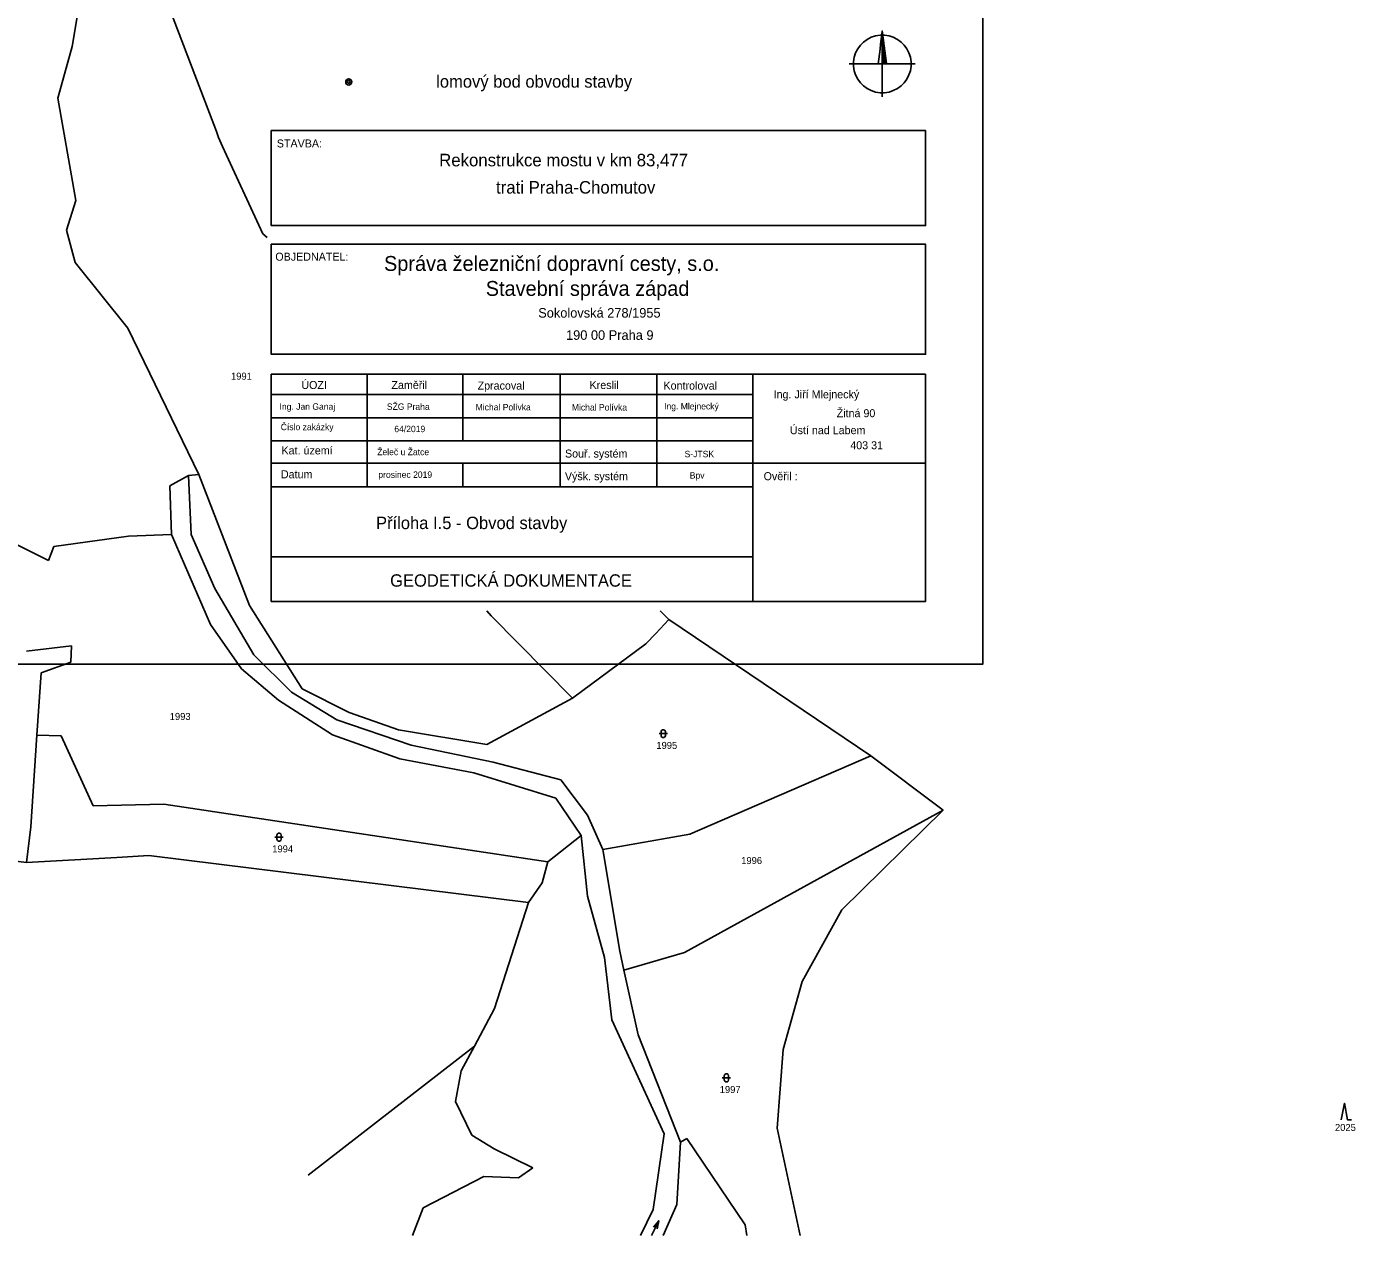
# Model space of a CAD drawing. Extents: x -801853 to -800578, y -1017479 to -1016338.
# Drawn here: x -800950 to -800627.9, y -1017477.7 to -1017184.4 of the extents above; entities that cross this region are included whole.
import ezdxf

# ---------------------------------------------------------------- set-up
doc = ezdxf.new("R2010")
doc.units = 0
for name, color, linetype in [('body', 7, 'Continuous'), ('Default', 7, 'Continuous'), ('KN_HRANICE', 7, 'Continuous'), ('KN_KULTURY', 7, 'Continuous'), ('KN_PARCELY', 7, 'Continuous'), ('LEGENDA', 7, 'Continuous'), ('tabulka', 7, 'Continuous')]:
    doc.layers.add(name, color=color, linetype=linetype)

# ---------------------------------------------------------------- blocks, each defined once
blk = doc.blocks.new('308')
at = {"layer": 'Default'}
blk.add_lwpolyline([(-0.75, 0), (0, 4), (0.75, 0), (1.75, 0)], dxfattribs=at)
blk = doc.blocks.new('316')
at = {"layer": 'Default'}
for points in [[(-1, 1), (0.27, 1), (1, 1)], [(-0.5, 1.5), (-0.4, 1.79), (-0.15, 1.97), (0.16, 1.97), (0.41, 1.79), (0.51, 1.5), (0.51, 0.5), (0.41, 0.21), (0.16, 0.03), (-0.15, 0.03), (-0.4, 0.21), (-0.5, 0.5), (-0.5, 1.5)]]:
    blk.add_lwpolyline(points, dxfattribs=at)
blk = doc.blocks.new('SEVER')
at = {"layer": 'Default'}
for points in [[(5.5, 69.8), (16.3, 68.1), (26.7, 64.7), (36.5, 59.7), (45.4, 53.2), (53.2, 45.4), (59.7, 36.5), (64.7, 26.7), (68.1, 16.3), (69.8, 5.5), (69.8, -5.5), (68.1, -16.3), (64.7, -26.7), (59.7, -36.5), (53.2, -45.4), (45.4, -53.2), (36.5, -59.7), (26.7, -64.7), (16.3, -68.1), (5.5, -69.8), (-5.5, -69.8), (-16.3, -68.1), (-26.7, -64.7), (-36.5, -59.7), (-45.4, -53.2), (-53.2, -45.4), (-59.7, -36.5), (-64.7, -26.7), (-68.1, -16.3), (-69.8, -5.5), (-69.8, 5.5), (-68.1, 16.3), (-64.7, 26.7), (-59.7, 36.5), (-53.2, 45.4), (-45.4, 53.2), (-36.5, 59.7), (-26.7, 64.7), (-16.3, 68.1), (-5.5, 69.8), (5.5, 69.8)], [(-10, 0), (-8.5, 12), (-7, 24), (-5.5, 36), (-4, 48), (-2.5, 60), (-1, 72), (0, 80), (1.5, 68), (3, 56), (4.5, 44), (6, 32), (7.5, 20), (9, 8), (10, 0), (9.2, 0.8), (9.2, 5.6), (8.4, 12), (8.4, 0.8), (7.6, 0.8), (7.6, 13.5), (7.6, 18.4), (6.8, 24.8), (6.8, 12.1), (6.8, 0.8), (6, 0.8), (6, 13.5), (6, 26.2), (6, 31.2), (5.2, 36.8), (5.2, 24.1), (5.2, 11.4), (5.2, 0.8), (4.4, 0.8), (4.4, 13.5), (4.4, 26.2), (4.4, 38.9), (4.4, 43.2), (3.6, 50.4), (3.6, 37.7), (3.6, 25), (3.6, 12.3), (3.6, 0.8), (2.8, 0.8), (2.8, 13.5), (2.8, 26.2), (2.8, 38.9), (2.8, 51.6), (2.8, 56), (2, 63.2), (2, 50.5), (2, 37.8), (2, 25.1), (2, 12.4), (2, 0.8), (1.2, 0.8), (1.2, 13.5), (1.2, 26.2), (1.2, 38.9), (1.2, 51.6), (1.2, 64.3), (1.2, 69.6), (0.4, 76), (0.4, 63.3), (0.4, 50.6), (0.4, 37.9), (0.4, 25.2), (0.4, 12.5), (0.4, 0.8)], [(0, 80), (0, 67.3), (0, 54.6), (0, 41.9), (0, 29.2), (0, 16.5), (0, 3.8), (0, -8.9), (0, -21.6), (0, -34.3), (0, -47), (0, -59.7), (0, -72.4), (0, -80)], [(80, 0), (67.3, 0), (54.6, 0), (41.9, 0), (29.2, 0), (16.5, 0), (3.8, 0), (-8.9, 0), (-21.6, 0), (-34.3, 0), (-47, 0), (-59.7, 0), (-72.4, 0), (-80, 0)]]:
    blk.add_lwpolyline(points, dxfattribs=at)

msp = doc.modelspace()

# ---------------------------------------------------------------- linework, layer by layer
at = {"layer": 'body'}
for radius in [0.75, 0.35]:
    msp.add_circle((-800871.92, -1017197.87), radius, dxfattribs=at)
at = {"layer": 'KN_HRANICE'}
for p, q in [((-800939.01, -1017189.32), (-800936.68, -1017175.71)), ((-800904.03, -1017209.93), (-800916.2, -1017177.92)), ((-800942.43, -1017201.78), (-800939.01, -1017189.32)), ((-800938.06, -1017226.62), (-800942.43, -1017201.78)), ((-800904.03, -1017209.93), (-800903.5, -1017211.33)), ((-800903.5, -1017211.33), (-800902.5, -1017213.51)), ((-800902.5, -1017213.51), (-800892.76, -1017234.71)), ((-800940.38, -1017233.81), (-800938.06, -1017226.62)), ((-800938.23, -1017241.65), (-800940.38, -1017233.81)), ((-800892.76, -1017234.71), (-800891.71, -1017235.57)), ((-800925.53, -1017257.6), (-800938.23, -1017241.65)), ((-800908.25, -1017293.09), (-800925.53, -1017257.6)), ((-800915.3, -1017295.86), (-800910.8, -1017293.37)), ((-800910.8, -1017293.37), (-800908.25, -1017293.09)), ((-800910.14, -1017307.62), (-800910.8, -1017293.37)), ((-800908.25, -1017293.09), (-800895.98, -1017324.86)), ((-800914.93, -1017307.65), (-800915.3, -1017295.86)), ((-800943.44, -1017310.57), (-800925.36, -1017308.04)), ((-800925.36, -1017308.04), (-800914.93, -1017307.65)), ((-800914.93, -1017307.65), (-800905.45, -1017329.47)), ((-800904.4, -1017320.71), (-800910.14, -1017307.62)), ((-800955.36, -1017308.64), (-800944.74, -1017313.92)), ((-800944.74, -1017313.92), (-800943.44, -1017310.57)), ((-800894.96, -1017336.82), (-800904.4, -1017320.71)), ((-800895.98, -1017324.86), (-800883.2, -1017345.04)), ((-800838.41, -1017326.15), (-800837.42, -1017327.39)), ((-800837.42, -1017327.39), (-800817.72, -1017347.38)), ((-800796.41, -1017326.15), (-800794.33, -1017328.28)), ((-800905.45, -1017329.47), (-800897.94, -1017340.24)), ((-800797.47, -1017331.62), (-800794.33, -1017328.28)), ((-800794.33, -1017328.28), (-800745.35, -1017361.29)), ((-800799.89, -1017334.2), (-800797.47, -1017331.62)), ((-800939.16, -1017334.66), (-800950.06, -1017335.93)), ((-800939.29, -1017338.64), (-800939.16, -1017334.66)), ((-800885.82, -1017345.89), (-800894.96, -1017336.82)), ((-800817.72, -1017347.38), (-800799.89, -1017334.2)), ((-800946.53, -1017341.16), (-800939.29, -1017338.64)), ((-800897.94, -1017340.24), (-800888.98, -1017347.84)), ((-800946.53, -1017341.16), (-800947.54, -1017356.33)), ((-800874.85, -1017352.61), (-800885.82, -1017345.89)), ((-800883.2, -1017345.04), (-800871.81, -1017350.85)), ((-800888.98, -1017347.84), (-800875.89, -1017356.2)), ((-800838.46, -1017358.55), (-800817.72, -1017347.38)), ((-800856.81, -1017358.7), (-800874.85, -1017352.61)), ((-800871.81, -1017350.85), (-800859.86, -1017355.03)), ((-800947.54, -1017356.33), (-800949.01, -1017378.54)), ((-800941.67, -1017356.46), (-800947.54, -1017356.33)), ((-800941.67, -1017356.46), (-800933.89, -1017373.43)), ((-800875.89, -1017356.2), (-800859.52, -1017362.06)), ((-800859.86, -1017355.03), (-800838.46, -1017358.55)), ((-800836.88, -1017362.87), (-800856.81, -1017358.7)), ((-800859.52, -1017362.06), (-800841.58, -1017365.44)), ((-800820.52, -1017367.14), (-800836.88, -1017362.87)), ((-800789.24, -1017380.33), (-800745.35, -1017361.29)), ((-800745.35, -1017361.29), (-800727.83, -1017374.48)), ((-800841.58, -1017365.44), (-800821.72, -1017371.63)), ((-800814.02, -1017375.7), (-800820.52, -1017367.14)), ((-800821.72, -1017371.63), (-800815.6, -1017380.62)), ((-800933.89, -1017373.43), (-800916.78, -1017373.03)), ((-800916.78, -1017373.03), (-800823.68, -1017387.02)), ((-800810.29, -1017384.01), (-800814.02, -1017375.7)), ((-800790.52, -1017409.01), (-800727.83, -1017374.48)), ((-800727.83, -1017374.48), (-800752.41, -1017398.66)), ((-800949.01, -1017378.54), (-800950.02, -1017387.19)), ((-800823.68, -1017387.02), (-800815.6, -1017380.62)), ((-800815.6, -1017380.62), (-800814.01, -1017395.39)), ((-800810.29, -1017384.01), (-800789.24, -1017380.33)), ((-800969.41, -1017384.77), (-800950.02, -1017387.19)), ((-800806.21, -1017408.67), (-800810.29, -1017384.01)), ((-800950.02, -1017387.19), (-800928.14, -1017385.96)), ((-800928.14, -1017385.96), (-800920.37, -1017385.53)), ((-800920.37, -1017385.53), (-800828.38, -1017396.89)), ((-800823.68, -1017387.02), (-800825.04, -1017392.1)), ((-800825.04, -1017392.1), (-800828.38, -1017396.89)), ((-800828.38, -1017396.89), (-800836.59, -1017422.58)), ((-800814.01, -1017395.39), (-800809.89, -1017410.22)), ((-800752.41, -1017398.66), (-800762, -1017416.1)), ((-800809.89, -1017410.22), (-800808.14, -1017425.35)), ((-800805.21, -1017413.29), (-800806.21, -1017408.67)), ((-800805.21, -1017413.29), (-800790.52, -1017409.01)), ((-800801.79, -1017429.03), (-800805.21, -1017413.29)), ((-800762, -1017416.1), (-800766.63, -1017432.59)), ((-800836.59, -1017422.58), (-800841.46, -1017431.73)), ((-800808.14, -1017425.35), (-800795.44, -1017452.98)), ((-800791.46, -1017455.01), (-800801.79, -1017429.03)), ((-800881.75, -1017463.05), (-800841.46, -1017431.73)), ((-800841.46, -1017431.73), (-800844.67, -1017437.76)), ((-800766.63, -1017432.59), (-800768.04, -1017451.67)), ((-800844.67, -1017437.76), (-800846.03, -1017445.14)), ((-800846.03, -1017445.14), (-800842.06, -1017453.34)), ((-800795.44, -1017452.98), (-800798.1, -1017471.37)), ((-800768.04, -1017451.67), (-800762.46, -1017477.65)), ((-800842.06, -1017453.34), (-800836.67, -1017456.66)), ((-800792.36, -1017470.15), (-800791.46, -1017455.01)), ((-800789.98, -1017454.15), (-800791.46, -1017455.01)), ((-800775.83, -1017475.04), (-800789.98, -1017454.15)), ((-800836.67, -1017456.66), (-800827.29, -1017461.28)), ((-800827.29, -1017461.28), (-800830.74, -1017463.67)), ((-800839.17, -1017463.36), (-800853.88, -1017470.95)), ((-800830.74, -1017463.67), (-800839.17, -1017463.36)), ((-800853.88, -1017470.95), (-800856.51, -1017477.65)), ((-800798.1, -1017471.37), (-800801.22, -1017477.65)), ((-800795.67, -1017477.65), (-800792.36, -1017470.15)), ((-800775.45, -1017477.65), (-800775.83, -1017475.04))]:
    msp.add_line(p, q, dxfattribs=at)
at = {"layer": 'KN_KULTURY'}
msp.add_line((-800798.5, -1017477.65), (-800796.76, -1017474.07), dxfattribs=at)
msp.add_lwpolyline([(-800798.08, -1017475.65), (-800796.76, -1017474.07), (-800797.18, -1017476.09)], dxfattribs=at)
at = {"layer": 'LEGENDA'}
msp.add_lwpolyline([(-801559.16, -1017339.08), (-800718.16, -1017339.08), (-800718.16, -1016745.08), (-801559.16, -1016745.08)], close=True, dxfattribs=at)
at = {"layer": 'tabulka'}
for p, q in [((-800890.72, -1017268.75), (-800732.06, -1017268.75)), ((-800867.43, -1017268.75), (-800867.43, -1017296.07)), ((-800844.28, -1017268.75), (-800844.28, -1017284.95)), ((-800820.68, -1017268.75), (-800820.68, -1017296.07)), ((-800797.23, -1017268.75), (-800797.23, -1017296.07)), ((-800773.93, -1017323.89), (-800773.93, -1017268.75)), ((-800890.72, -1017273.66), (-800773.93, -1017273.66)), ((-800890.72, -1017279.38), (-800773.93, -1017279.38)), ((-800890.72, -1017284.95), (-800773.93, -1017284.95)), ((-800890.72, -1017290.37), (-800732.06, -1017290.37)), ((-800844.28, -1017290.37), (-800844.28, -1017296.07)), ((-800890.72, -1017296.07), (-800773.93, -1017296.07)), ((-800890.72, -1017313.07), (-800773.93, -1017313.07))]:
    msp.add_line(p, q, dxfattribs=at)
for points in [[(-800890.72, -1017209.67), (-800732.06, -1017209.67), (-800732.06, -1017232.73), (-800890.72, -1017232.73)], [(-800890.72, -1017237.25), (-800732.06, -1017237.25), (-800732.06, -1017263.94), (-800890.72, -1017263.94)]]:
    msp.add_lwpolyline(points, close=True, dxfattribs=at)
msp.add_lwpolyline([(-800732.06, -1017268.75), (-800732.06, -1017323.89), (-800890.72, -1017323.89), (-800890.72, -1017268.75)], dxfattribs=at)

# ---------------------------------------------------------------- block references
at = {"layer": 'KN_KULTURY'}
for name, p in [('316', (-800795.67, -1017356.95)), ('316', (-800888.84, -1017382.04)), ('316', (-800780.38, -1017440.41)), ('308', (-800630.53, -1017449.61))]:
    msp.add_blockref(name, p, dxfattribs=at)
at = {"layer": 'LEGENDA', "xscale": 0.1, "yscale": 0.10000000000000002}
msp.add_blockref('SEVER', (-800742.57, -1017193.52), dxfattribs=at)

# ---------------------------------------------------------------- texts
at = {"layer": 'KN_PARCELY'}
for s, p in [('1991', (-800900.48, -1017270.1)), ('1993', (-800915.33, -1017352.62)), ('1995', (-800797.35, -1017359.65)), ('1994', (-800890.48, -1017384.74)), ('1996', (-800776.78, -1017387.58)), ('1997', (-800781.98, -1017443.11)), ('2025', (-800632.82, -1017452.31))]:
    msp.add_text(s, height=1.7, dxfattribs=at).set_placement(p)
at = {"layer": 'LEGENDA'}
msp.add_text('lomový bod obvodu stavby', height=3, dxfattribs=at).set_placement((-800850.73, -1017199.26))
at = {"layer": 'tabulka'}
for s, height, p in [('STAVBA:', 1.94, (-800889.37, -1017213.77)), ('Rekonstrukce mostu v km 83,477', 3.04, (-800850, -1017218.35)), ('trati Praha-Chomutov', 3.04, (-800836.22, -1017224.96)), ('OBJEDNATEL:', 1.94, (-800889.73, -1017241.23)), ('Správa železniční dopravní cesty, s.o.', 3.61, (-800863.38, -1017243.71)), ('Stavební správa západ', 3.61, (-800838.71, -1017249.77)), ('Sokolovská 278/1955', 2.32, (-800825.99, -1017255.04)), ('190 00 Praha 9', 2.32, (-800819.25, -1017260.43)), ('ÚOZI', 1.94, (-800883.42, -1017272.35)), ('Zaměřil', 1.94, (-800861.58, -1017272.35)), ('Zpracoval', 1.94, (-800840.69, -1017272.5)), ('Kreslil', 1.94, (-800813.53, -1017272.35)), ('Kontroloval', 1.94, (-800795.62, -1017272.5)), ('Ing. Jiří Mlejnecký', 1.94, (-800768.92, -1017274.61)), ('Ing. Jan Ganaj', 1.552, (-800888.71, -1017277.39)), ('SŽG Praha', 1.552, (-800862.69, -1017277.41)), ('Michal Polívka', 1.552, (-800841.17, -1017277.54)), ('Michal Polívka', 1.552, (-800817.84, -1017277.57)), ('Ing. Mlejnecký', 1.552, (-800795.47, -1017277.31)), ('Žitná 90', 1.94, (-800753.63, -1017279.19)), ('Číslo zakázky', 1.552, (-800888.41, -1017282.34)), ('64/2019', 1.552, (-800860.88, -1017282.82)), ('Ústí nad Labem', 1.94, (-800764.97, -1017283.31)), ('403 31', 1.94, (-800750.33, -1017286.97)), ('Kat. území', 1.94, (-800888.23, -1017288.22)), ('Želeč u Žatce', 1.552, (-800865.02, -1017288.41)), ('Souř. systém', 1.94, (-800819.5, -1017288.98)), ('S-JTSK', 1.552, (-800790.51, -1017288.9)), ('Datum', 1.94, (-800888.37, -1017294.01)), ('prosinec 2019', 1.552, (-800864.75, -1017293.9)), ('Výšk. systém', 1.94, (-800819.52, -1017294.47)), ('Bpv', 1.552, (-800789.25, -1017294.08)), ('Ověřil :', 1.94, (-800771.34, -1017294.47)), ('Příloha I.5 - Obvod stavby', 3, (-800865.32, -1017306.33)), ('GEODETICKÁ DOKUMENTACE ', 3, (-800861.9, -1017320.3))]:
    msp.add_text(s, height=height, dxfattribs=at).set_placement(p)

doc.saveas('drawing.dxf')
